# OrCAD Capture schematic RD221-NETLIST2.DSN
size A3
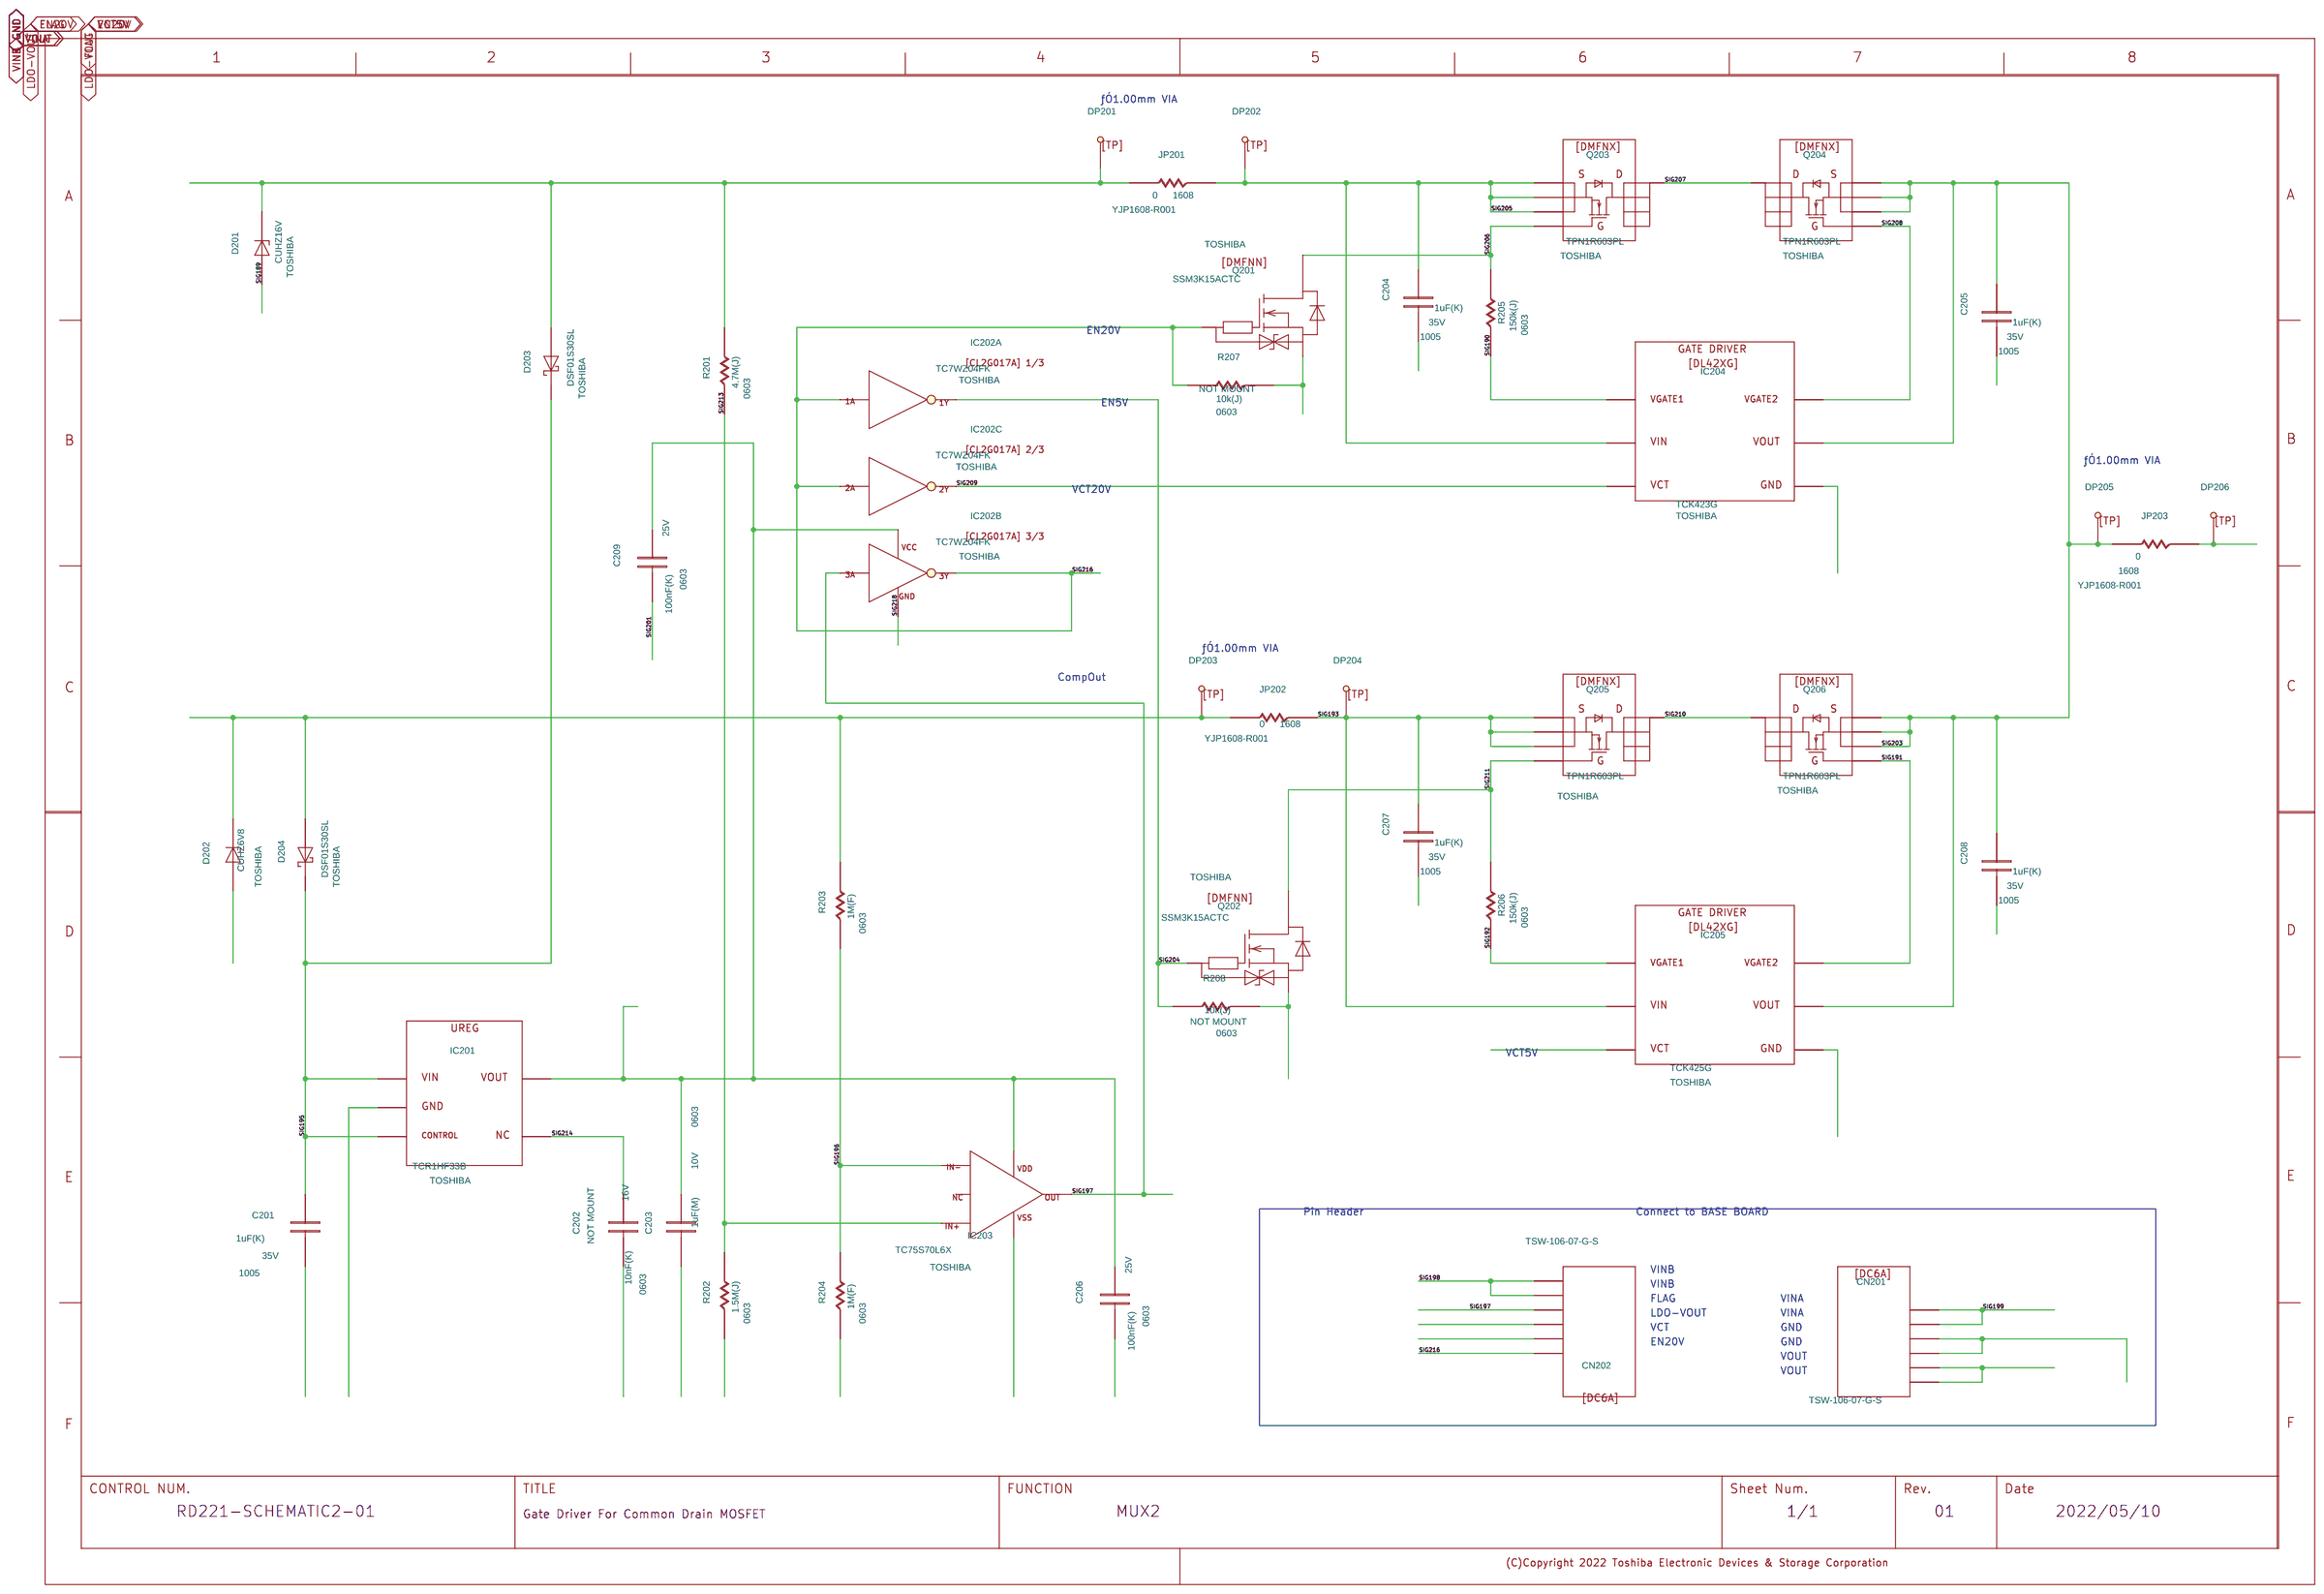
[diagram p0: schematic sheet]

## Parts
C201  DC
C202  DC
C203  DC
C204  DC
C205  DC
C206  DC
C207  DC
C208  DC
C209  DC
CN201  DC6A
CN202  DC6A
D201  DZD
D202  DZD
D203  DSBD
D204  DSBD
DP201  DTP
DP202  DTP
DP203  DTP
DP204  DTP
DP205  DTP
DP206  DTP
IC201  DL1HFXX
IC202  TC7WZ04FK_1  (sections A,B,C)
IC203  TC75S70L6X
IC204  DL42XG
IC205  DL42XG
JP201  DR
JP202  DR
JP203  DR
Q201  DMFNN
Q202  DMFNN
Q203  DMFNX
Q204  DMFNX
Q205  DMFNX
Q206  DMFNX
R201  DR
R202  DR
R203  DR
R204  DR
R205  DR
R206  DR
R207  DR
R208  DR
U?#1  WAKU_DEF100

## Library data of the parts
C201 C204 C205 C207 C208 = DC: COMP: DP0000016125; COMPONENTNAME: DP0000016125_package; FUNCN: DP0000016125; GCOUNT: 1; MAXGCOUNT: 1; OUMEPARTTYPE: C; SIZECODESMD: 1005; VAL1: 1uF(K); VAL2: 35V; VAL3: GRM155R6YA105KE11D
C202 = DC: COMP: DP0010383000; COMPONENTNAME: DP0010383000_package; FUNCN: DP0010383000; GCOUNT: 1; MAXGCOUNT: 1; NOTMOUNT: NOT MOUNT; OUMEPARTTYPE: C; SIZECODESMD: 0603; VAL1: 10nF(K); VAL2: 16V; VAL3: GRM033R71C103KE14D
C203 = DC: COMP: DP0007093000; COMPONENTNAME: DP0007093000_package; FUNCN: DP0007093000; GCOUNT: 1; MAXGCOUNT: 1; OUMEPARTTYPE: C; SIZECODESMD: 0603; VAL1: 1uF(M); VAL2: 10V; VAL3: GRM033R61A105ME15D
C206 C209 = DC: COMP: DP0000015403; COMPONENTNAME: DP0000015403_package; FUNCN: DP0000015403; GCOUNT: 1; MAXGCOUNT: 1; OUMEPARTTYPE: C; SIZECODESMD: 0603; VAL1: 100nF(K); VAL2: 25V; VAL3: GRM033R61E104KE14D
CN201 CN202 = DC6A: COMP: DP0010563000; COMPONENTNAME: DP0010563000_package; FUNCN: DP0010563000; GCOUNT: 1; MAXGCOUNT: 1; OUMEPARTTYPE: CN; VAL3: TSW-106-07-G-S
D201 = DZD: COMP: DP0010580000; COMPONENTNAME: DP0010580000_package; FUNCN: DP0010580000; GCOUNT: 1; MAXGCOUNT: 1; OUMEPARTTYPE: D; USERCOMPTEXT3: TOSHIBA; VAL1: CUHZ16V; VAL3: CUHZ16V
D202 = DZD: COMP: DP0010558000; COMPONENTNAME: DP0010558000_package; FUNCN: DP0010558000; GCOUNT: 1; MAXGCOUNT: 1; OUMEPARTTYPE: D; USERCOMPTEXT3: TOSHIBA; VAL1: CUHZ6V8; VAL3: CUHZ6V8
D203 D204 = DSBD: COMP: DP0010560000; COMPONENTNAME: DP0010560000_package; FUNCN: DP0010560000; GCOUNT: 1; MAXGCOUNT: 1; OUMEPARTTYPE: D; USERCOMPTEXT3: TOSHIBA; VAL1: DSF01S30SL; VAL3: DSF01S30SL
DP201-DP206 = DTP: COMP: DP9000817000; COMPONENTNAME: DP9000817000_package; FUNCN: DP9000817000; GCOUNT: 1; MAXGCOUNT: 1; NOTMOUNT: NOT MOUNT; OUMEPARTTYPE: TP
IC201 = DL1HFXX: COMP: DP0008120000; COMPONENTNAME: DP0008120000_package; FUNCN: DP0008120000; SAVEAREA0: -37394,-7797,68343,35643; SAVECOUNT: 26; UPDATEDATE: 2021/11/24; UPDATETIME: 10:48:25; UPDATEUSER: w90028dm; USERCOMPTEXT3: TOSHIBA; VAL1: TCR1HF33B; VAL3: TCR1HF33B
IC202 = TC7WZ04FK_1: COMP: DP0001429000; CaptureCellPackProp: TC7WZ04FK_1A; FUNCN: DP0001429000_1; USERCOMPTEXT3: TOSHIBA; VAL1: TC7WZ04FK; VAL3: TC7WZ04FK
IC203 = TC75S70L6X: COMP: DP0010561000; FUNCN: DP0010561000; USERCOMPTEXT3: TOSHIBA
IC204 = DL42XG: COMP: DP0010579000; COMPONENTNAME: DP0010579000_package; FUNCN: DP0010579000; GCOUNT: 1; MAXGCOUNT: 1; OUMEPARTTYPE: IC; SAVEAREA0: 0,-2569,38100,25362; UPDATEDATE: 2021/11/09; UPDATETIME: 14:52:41; UPDATEUSER: t5459927; USERCOMPTEXT3: TOSHIBA; VAL1: TCK423G; VAL3: TCK423G
IC205 = DL42XG: COMP: DP0010556000; COMPONENTNAME: DP0010556000_package; FUNCN: DP0010556000; GCOUNT: 1; MAXGCOUNT: 1; OUMEPARTTYPE: IC; SAVEAREA0: -5715,0,43876,22860; UPDATEDATE: 2021/11/09; UPDATETIME: 13:49:24; UPDATEUSER: t5459927; USERCOMPTEXT3: TOSHIBA; VAL1: TCK425G; VAL3: TCK425G
JP201-JP203 = DR: COMP: DP0001376000; COMPCOMMENT: 0; COMPONENTNAME: DP0001376000_package; FUNCN: DP0001376000; GCOUNT: 1; MAXGCOUNT: 1; OUMEPARTTYPE: R; SIZECODESMD: 1608; VAL1: 200u(X); VAL2: 30mW; VAL3: YJP1608-R001
Q201 Q202 = DMFNN: COMP: DP0010513000; COMPONENTNAME: DP0010513000_package; DEVICE: RN4905; DEVICENAME: RN49A1FE(TE85L); FUNCN: DP0010513000; FUNCTION: PNP&NPN_PCT; GCOUNT: 1; HETERO: RN4905_1,RN4905_2; LEVEL: STD; MAXGCOUNT: 1; OUMEPARTTYPE: Q; P/D_NUM: TOSHIBA; PARTS: 1; PKG_TYPE: 2-2J1A; SAVEAREA0: -41191,-19664,61952,27881; UPDATEDATE: 2021/11/11; UPDATETIME: 08:00:04; UPDATEUSER: t5459927; USERCOMPTEXT3: TOSHIBA; VAL1: SSM3K15ACTC; VAL3: SSM3K15ACTC
Q203-Q206 = DMFNX: ADSCNVFLAG: ON; ADSCOMPONENTNAME: Q_DMFNX; ADSMODELNAME: s_TPHR6503PL1; CDMASTERCADCELG: SN1026; COMP: DP0010582000; COMPONENTNAME: DP0010562000_package; FNLEADFREETHET1GT2GMCTH1: N_N_N; FUNCN: DP0010562000; GCOUNT: 1; MAXDRAINCURRENT: 420; MAXDSVOLTAGE: 30; MAXGCOUNT: 1; MOUNTINGFORMSMD: SMD; OUMECLASSIFICATION: m`llnr|eds; OUMEMAKER: TSB “ŒŽÅ; OUMEMAKERKATAMEI: TPHR6503PL1; OUMEPARTTYPE: Q; USERCOMPTEXT3: TOSHIBA; VAL1: TPN1R603PL; VAL3: TPN1R603PL
R201 = DR: COMP: DP0000151160; COMPONENTNAME: DP0000151160; FUNCN: DP0000151160; GCOUNT: 1; MAXGCOUNT: 1; OUMEPARTTYPE: R; SIZECODESMD: 0603; VAL1: 4.7M(J); VAL2: 50mW; VAL3: ERJ1GNJ475C
R202 = DR: COMP: DP0000151148; COMPONENTNAME: DP0000151148; FUNCN: DP0000151148; GCOUNT: 1; MAXGCOUNT: 1; OUMEPARTTYPE: R; SIZECODESMD: 0603; VAL1: 1.5M(J); VAL2: 50mW; VAL3: ERJ1GNJ155C
R203 R204 = DR: COMP: DP0000152120; COMPONENTNAME: DP0000152120; FUNCN: DP0000152120; GCOUNT: 1; MAXGCOUNT: 1; OUMEPARTTYPE: R; SIZECODESMD: 0603; VAL1: 1M(F); VAL2: 50mW; VAL3: ERJ1GNF1004C
R205 R206 = DR: COMP: DP0000155124; COMPONENTNAME: DP0000155124; FUNCN: DP0000155124; GCOUNT: 1; MAXGCOUNT: 1; OUMEPARTTYPE: R; SIZECODESMD: 0603; VAL1: 150k(J); VAL2: 50mW; VAL3: RK73B1HTTC154J
R207 R208 = DR: COMP: DP0002867000; COMPONENTNAME: DP0002867000_package; FUNCN: DP0002867000; GCOUNT: 1; MAXGCOUNT: 1; NOTMOUNT: NOT MOUNT; OUMEPARTTYPE: R; SIZECODESMD: 0603; VAL1: 10k(J); VAL2: 50mW; VAL3: RK73B1HTTCM103J
U?#1 = WAKU_DEF100: DATE: 2022/05/10; DRAWINGNUMBER: RD221-SCHEMATIC2-01; FUNCTION: MUX2; REVISION: 01; SAVEAREA0: 148187,-66180,486823,89919; SAVECOUNT: 6; SHEETNUMBER: 1/1; TITLE: Gate Driver For Common Drain MOSFET; UPDATEDATE: 2022/05/17; UPDATETIME: 07:13:03

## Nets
GND: C201.2 C202.2 C203.2 C204.2 C205.2 C206.2 C207.2 C208.2 C209.2 CN201.3 CN201.4 D201.A D202.A IC201.2 IC202.4 IC203.2 IC204.B2 IC205.B2 Q201.S Q202.S R202.2 R204.2 R207.2 R208.2
VINA: CN201.1 CN201.2 D201.C D203.A DP201.1 JP201.1 R201.1
VINB: CN202.5 CN202.6 D202.C D204.A DP203.1 JP202.1 R203.1
EN20V: CN202.1 IC202.1 IC202.2 IC202.3 Q201.G R207.1
FLAG: CN202.4 IC202.6 IC203.1
LDO-VOUT: C203.1 C206.1 C209.1 CN202.3 IC201.5 IC202.8 IC203.6
SIG190: IC204.A1 R205.2
SIG191: IC205.B1 Q206.4
SIG192: IC205.A1 R206.2
SIG193: C207.1 DP204.1 IC205.A2 JP202.2 Q205.1 Q205.2 Q205.3
SIG195: C201.1 D203.C D204.C IC201.1 IC201.3
SIG196: IC203.4 R203.2 R204.1
SIG203: C205.1 C208.1 DP205.1 IC204.C1 IC205.C1 JP203.1 Q204.1 Q204.2 Q204.3 Q206.1 Q206.2 Q206.3
SIG204: IC202.7 Q202.G R208.1
SIG205: C204.1 DP202.1 IC204.A2 JP201.2 Q203.1 Q203.2 Q203.3
SIG206: Q201.D Q203.4 R205.1
SIG207: Q203.5 Q204.5
SIG208: IC204.B1 Q204.4
SIG209: IC202.5 IC204.C2
SIG210: Q205.5 Q206.5
SIG211: Q202.D Q205.4 R206.1
SIG213: IC203.3 R201.2 R202.1
SIG214: C202.1 IC201.4
VCT5V: CN202.2 IC205.C2
VOUT: CN201.5 CN201.6 DP206.1 JP203.2

Not connected (* = marked no-connect by the designer): IC203 5

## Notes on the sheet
- ƒÓ1.00mm VIA
- EN20V
- EN5V
- ƒÓ1.00mm VIA
- VCT20V
- ƒÓ1.00mm VIA
- CompOut
- VCT5V
- Pin Header
- Connect to BASE BOARD
- VINB
- VINB
- FLAG
- VINA
- LDO-VOUT
- VINA
- VCT
- GND
- EN20V
- GND
- VOUT
- VOUT
